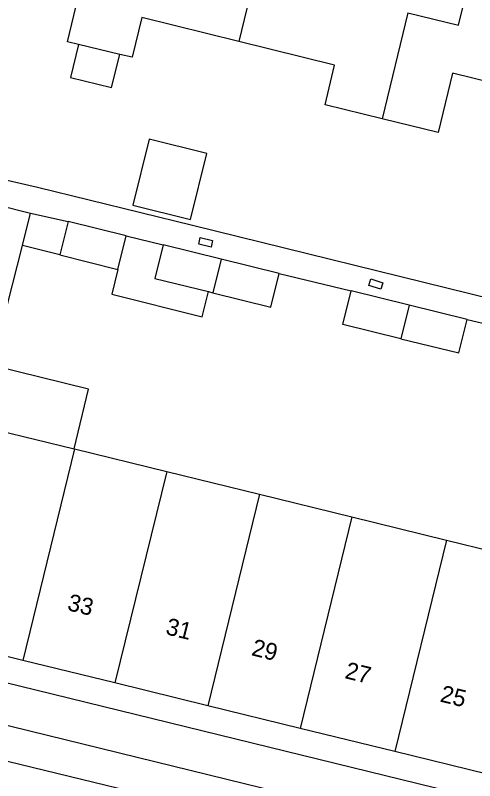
# Model space of a CAD drawing. Extents: x 125000 to 129004, y 397500 to 399008.
# Drawn here: x 126541.62 to 126568.71, y 397923.5 to 397968.6 of the extents above; entities that cross this region are included whole.
import ezdxf

# ---------------------------------------------------------------- set-up
doc = ezdxf.new("R2010")
doc.units = 0
for name, color, linetype in [('gg-afsc-erfafscheiding', 7, 'Continuous'), ('gg-afsc-hekwerk', 7, 'Continuous'), ('gg-anno-huisnummerreeks BGT', 7, 'Continuous'), ('gg-bbg-bijgebouw', 7, 'Continuous'), ('gg-bbg-gedigitaliseerde bebouwing', 7, 'Continuous'), ('gg-bbg-gedigitaliseerde bijgebouw', 7, 'Continuous'), ('gg-bbg-hoofdgebouw', 7, 'Continuous'), ('gg-bbg-luifel en loopbrug', 7, 'Continuous'), ('gg-bbg-tussenscheiding', 7, 'Continuous'), ('gg-knt-verharding', 7, 'Continuous'), ('gg-knt-verharding nz', 7, 'Continuous'), ('gt-grn-weggrens', 7, 'Continuous'), ('gt-symb-kolk center center', 7, 'Continuous')]:
    doc.layers.add(name, color=color, linetype=linetype)

# ---------------------------------------------------------------- blocks, each defined once
blk = doc.blocks.new('gt0-KOLKCC')
at = {"layer": 'gt-symb-kolk center center'}
blk.add_lwpolyline([(-0.375, 0.2), (0.375, 0.2), (0.375, -0.2), (-0.375, -0.2)], close=True, dxfattribs=at)

msp = doc.modelspace()

# ---------------------------------------------------------------- linework, layer by layer
at = {"layer": 'gg-afsc-erfafscheiding'}
for p, q in [((126540.599, 397959.003), (126542.932, 397958.478)), ((126552.071, 397956.227), (126573.07, 397951.058)), ((126557.179, 397953.39), (126561.421, 397952.365)), ((126568.259, 397950.682), (126570.375, 397950.174))]:
    msp.add_line(p, q, dxfattribs=at)
at = {"layer": 'gg-afsc-hekwerk'}
msp.add_line((126539.333, 397944.462), (126542.033, 397955.029), dxfattribs=at)
at = {"layer": 'gg-bbg-bijgebouw'}
for p, q in [((126544.73, 397956.457), (126544.237, 397954.479)), ((126548.162, 397955.602), (126544.73, 397956.457)), ((126547.669, 397953.623), (126548.162, 397955.602)), ((126553.756, 397954.237), (126550.342, 397955.082)), ((126544.237, 397954.479), (126547.669, 397953.623)), ((126557.179, 397953.39), (126553.756, 397954.237)), ((126553.012, 397952.318), (126553.271, 397952.254)), ((126564.838, 397951.524), (126561.421, 397952.365)), ((126568.259, 397950.682), (126564.838, 397951.524))]:
    msp.add_line(p, q, dxfattribs=at)
for points in [[(126550.342, 397955.082), (126549.852, 397953.098), (126553.012, 397952.318)], [(126553.271, 397952.254), (126556.689, 397951.41), (126557.179, 397953.39)], [(126564.352, 397949.543), (126560.933, 397950.384), (126561.421, 397952.365)], [(126564.352, 397949.543), (126567.771, 397948.701), (126568.259, 397950.682)]]:
    msp.add_lwpolyline(points, dxfattribs=at)
at = {"layer": 'gg-bbg-gedigitaliseerde bebouwing'}
for p, q in [((126545.351, 397966.882), (126544.688, 397967.042)), ((126548.501, 397966.123), (126547.782, 397966.296))]:
    msp.add_line(p, q, dxfattribs=at)
at = {"layer": 'gg-bbg-gedigitaliseerde bijgebouw'}
msp.add_lwpolyline([(126545.351, 397966.882), (126544.868, 397964.937), (126547.295, 397964.334), (126547.782, 397966.296)], dxfattribs=at)
at = {"layer": 'gg-bbg-hoofdgebouw'}
for p, q in [((126544.688, 397967.042), (126545.43, 397970.064)), ((126549.079, 397968.459), (126548.501, 397966.123)), ((126554.796, 397967.048), (126549.079, 397968.459)), ((126539.464, 397944.43), (126545.08, 397943.054)), ((126545.08, 397943.054), (126545.104, 397943.048)), ((126545.104, 397943.048), (126550.549, 397941.714)), ((126550.549, 397941.714), (126556.016, 397940.375)), ((126556.016, 397940.375), (126561.461, 397939.041)), ((126561.461, 397939.041), (126567.051, 397937.671)), ((126567.051, 397937.671), (126572.504, 397936.335)), ((126542.051, 397930.591), (126536.317, 397931.997)), ((126547.496, 397929.257), (126542.051, 397930.591)), ((126552.964, 397927.916), (126547.496, 397929.257)), ((126558.408, 397926.582), (126552.964, 397927.916)), ((126563.998, 397925.212), (126558.408, 397926.582)), ((126569.452, 397923.875), (126563.998, 397925.212))]:
    msp.add_line(p, q, dxfattribs=at)
for points in [[(126564.761, 397968.744), (126567.756, 397968.008), (126568.313, 397970.271), (126568.205, 397970.298), (126568.778, 397972.63), (126568.886, 397972.603), (126569.912, 397976.779), (126575.108, 397975.515), (126575.004, 397975.088), (126576.346, 397974.759), (126575.631, 397971.842), (126576.642, 397971.594), (126575.654, 397967.559), (126574.642, 397967.807), (126573.929, 397964.895)], [(126563.253, 397962.507), (126559.89, 397963.328), (126560.449, 397965.653), (126554.796, 397967.048)], [(126573.929, 397964.895), (126573.627, 397963.664), (126567.404, 397965.189), (126566.552, 397961.701), (126563.253, 397962.507)]]:
    msp.add_lwpolyline(points, dxfattribs=at)
at = {"layer": 'gg-bbg-luifel en loopbrug'}
for p, q in [((126542.033, 397955.029), (126542.519, 397956.932)), ((126542.519, 397956.932), (126544.73, 397956.457)), ((126548.162, 397955.602), (126550.342, 397955.082)), ((126544.237, 397954.479), (126542.033, 397955.029))]:
    msp.add_line(p, q, dxfattribs=at)
for points in [[(126551.949, 397956.566), (126552.913, 397960.449), (126549.516, 397961.292), (126548.552, 397957.409), (126551.949, 397956.566)], [(126547.669, 397953.623), (126547.306, 397952.168), (126552.643, 397950.837), (126553.012, 397952.318)], [(126545.08, 397943.054), (126545.941, 397946.57), (126540.326, 397947.948), (126539.464, 397944.43)]]:
    msp.add_lwpolyline(points, dxfattribs=at)
at = {"layer": 'gg-bbg-tussenscheiding'}
for p, q in [((126557.86, 397979.728), (126554.796, 397967.048)), ((126564.761, 397968.744), (126563.253, 397962.507)), ((126547.782, 397966.296), (126545.351, 397966.882)), ((126553.756, 397954.237), (126553.271, 397952.254)), ((126564.838, 397951.524), (126564.352, 397949.543)), ((126545.104, 397943.048), (126542.051, 397930.591)), ((126550.549, 397941.714), (126547.496, 397929.257)), ((126556.016, 397940.375), (126552.964, 397927.916)), ((126561.461, 397939.041), (126558.408, 397926.582)), ((126567.051, 397937.671), (126563.998, 397925.212))]:
    msp.add_line(p, q, dxfattribs=at)
at = {"layer": 'gg-knt-verharding'}
msp.add_line((126542.932, 397958.478), (126552.071, 397956.227), dxfattribs=at)
for points in [[(126535.979, 397930.532), (126659.361, 397900.329), (126665.374, 397898.886)], [(126529.258, 397927.574), (126529.715, 397929.557), (126608.024, 397910.375), (126607.541, 397908.385)]]:
    msp.add_lwpolyline(points, dxfattribs=at)
at = {"layer": 'gg-knt-verharding nz'}
msp.add_lwpolyline([(126607.541, 397908.385), (126595.597, 397911.185), (126579.956, 397915.125), (126564.162, 397918.959), (126547.703, 397923.035), (126532.333, 397926.769), (126529.258, 397927.574)], dxfattribs=at)
at = {"layer": 'gt-grn-weggrens'}
msp.add_line((126535.695, 397958.638), (126542.519, 397956.932), dxfattribs=at)

# ---------------------------------------------------------------- block references
at = {"layer": 'gt-symb-kolk center center'}
for p, rotation in [((126552.845, 397955.219), -13.063337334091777), ((126562.883, 397952.762), 162.85095611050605)]:
    msp.add_blockref('gt0-KOLKCC', p, dxfattribs=dict(at, rotation=rotation))

# ---------------------------------------------------------------- texts
at = {"layer": 'gg-anno-huisnummerreeks BGT'}
for s, p in [('33', (126544.635, 397933.561)), ('31', (126550.435, 397932.139)), ('29', (126555.496, 397930.899)), ('27', (126561.004, 397929.549)), ('25', (126566.619, 397928.173))]:
    msp.add_text(s, height=1, rotation=346.2, dxfattribs=at).set_placement(p)

doc.saveas('drawing.dxf')
